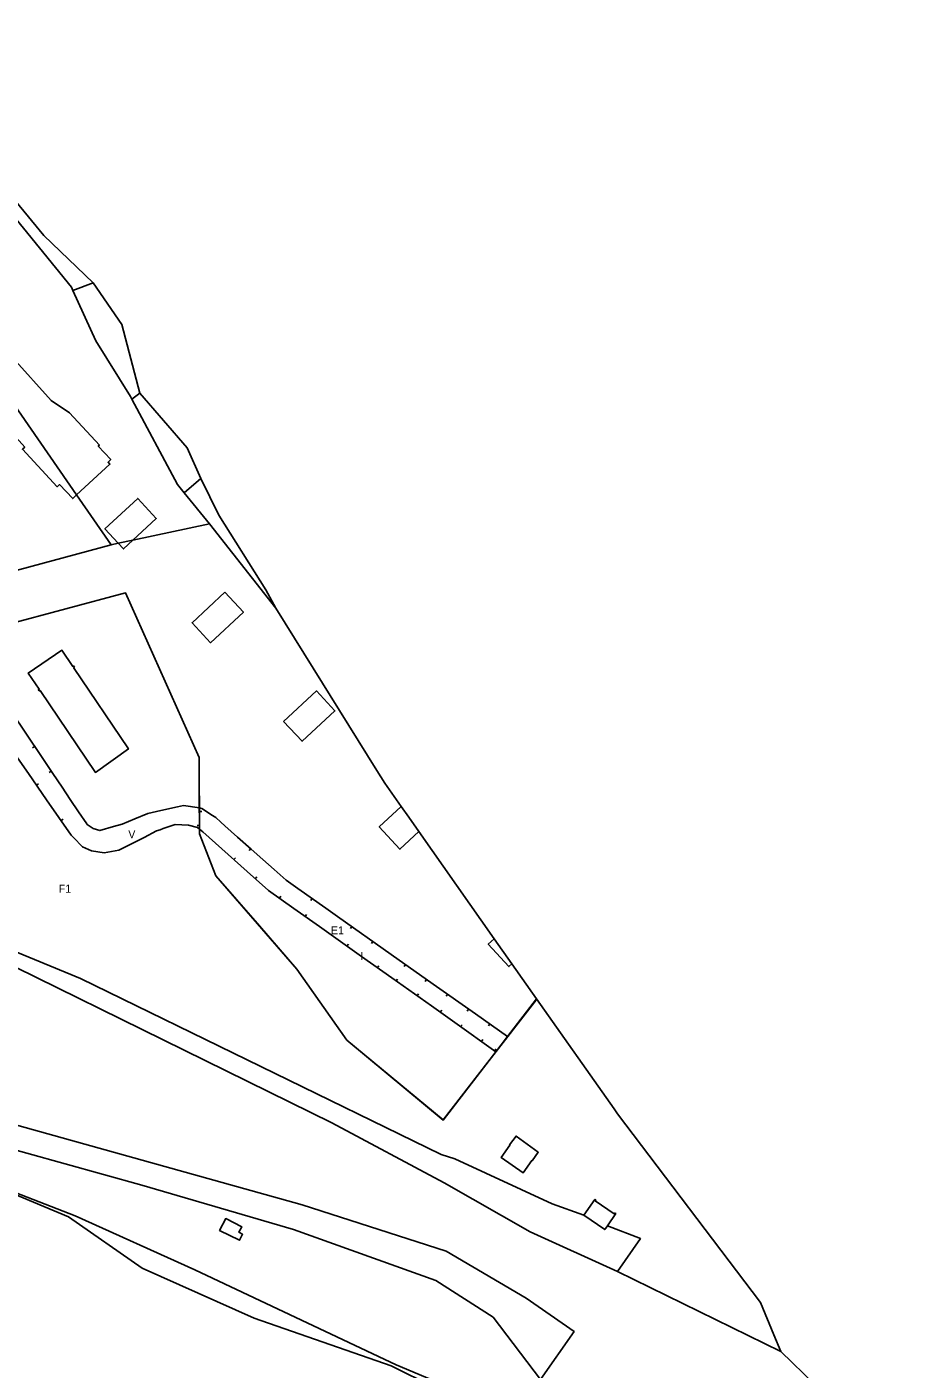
# Model space of a CAD drawing. Extents: x -749314 to -746497, y -1026537 to -1024935.
# Drawn here: x -747166.5 to -746888.2, y -1025946 to -1025526.8 of the extents above; entities that cross this region are included whole.
import ezdxf

# ---------------------------------------------------------------- set-up
doc = ezdxf.new("R2010")
doc.units = 0
for name, color, linetype in [('K_CD1', 7, 'Continuous'), ('K_DOSZDC1', 7, 'Continuous'), ('K_JVL', 7, 'Continuous'), ('K_NH_SZDC', 7, 'Continuous'), ('K_SZDC1', 7, 'Continuous'), ('K_VBP', 7, 'Continuous')]:
    doc.layers.add(name, color=color, linetype=linetype)

msp = doc.modelspace()

# ---------------------------------------------------------------- linework, layer by layer
for points in [[(-747164.06, -1025751.61), (-747164.69, -1025752.03)], [(-747158.89, -1025759.29), (-747159.51, -1025759.71)], [(-747163.47, -1025763.68), (-747162.85, -1025763.26)], [(-747112.61, -1025771.87), (-747111.86, -1025771.86)], [(-747155.8, -1025774.71), (-747155.18, -1025774.29)], [(-747112.58, -1025776.29), (-747113.33, -1025776.3)], [(-747101.81, -1025786.91), (-747101.31, -1025786.36)], [(-747096.56, -1025783.49), (-747097.06, -1025784.06)], [(-747095.15, -1025792.9), (-747094.65, -1025792.34)], [(-747087.65, -1025798.98), (-747087.22, -1025798.37)], [(-747077.37, -1025799.07), (-747077.81, -1025799.68)], [(-747079.64, -1025804.66), (-747079.2, -1025804.05)], [(-747064.99, -1025807.84), (-747065.43, -1025808.45)], [(-747066.53, -1025813.95), (-747066.09, -1025813.34)], [(-747058.46, -1025812.46), (-747058.9, -1025813.07)], [(-747057.06, -1025820.66), (-747056.62, -1025820.05)], [(-747048.23, -1025819.7), (-747048.66, -1025820.31)], [(-747051.2, -1025824.81), (-747050.77, -1025824.2)], [(-747041.69, -1025824.32), (-747042.12, -1025824.93)], [(-747044.67, -1025829.43), (-747044.24, -1025828.82)], [(-747035.09, -1025828.97), (-747035.53, -1025829.58)], [(-747037.39, -1025834.59), (-747036.95, -1025833.98)], [(-747028.55, -1025833.58), (-747028.99, -1025834.19)], [(-747031.04, -1025839.08), (-747030.61, -1025838.47)], [(-747021.96, -1025838.23), (-747022.39, -1025838.84)], [(-747024.52, -1025843.71), (-747024.08, -1025843.1)], [(-747019.74, -1025846.52), (-747020.34, -1025846.06)]]:
    msp.add_lwpolyline(points)
at = {"layer": 'K_CD1'}
for points in [[(-747145.79, -1025606.78), (-747161.2, -1025592.04), (-747186.31, -1025561.6), (-747208.9, -1025537.01), (-747217.97, -1025527.65), (-747211.2, -1025536.12), (-747152.53, -1025608.14), (-747152.08, -1025609.14)], [(-747200.27, -1025621.3), (-747167.16, -1025658.09), (-747167.86, -1025658.73), (-747156.98, -1025670.46), (-747156.24, -1025669.78), (-747152.14, -1025674.15), (-747150.94, -1025673.04), (-747185.44, -1025623.24), (-747188.83, -1025612.23), (-747194.35, -1025605.97), (-747201.01, -1025609.1), (-747196.13, -1025619.18)], [(-747131.2, -1025641.21), (-747136.83, -1025619.83), (-747145.79, -1025606.78), (-747152.08, -1025609.14), (-747144.94, -1025624.91), (-747134.13, -1025642.29), (-747133.71, -1025643.07)], [(-747180.93, -1025684.57), (-747178.68, -1025693.46), (-747204.73, -1025700.85), (-747205.8, -1025701.71), (-747198.39, -1025704.35), (-747140.17, -1025688.58), (-747150.94, -1025673.04), (-747152.14, -1025674.15), (-747156.24, -1025669.78), (-747156.98, -1025670.46), (-747167.86, -1025658.73), (-747167.16, -1025658.09), (-747200.27, -1025621.3), (-747211.67, -1025627.14), (-747214.25, -1025628.23), (-747203.49, -1025644.13), (-747199.44, -1025656.88), (-747194.73, -1025664.89), (-747194.07, -1025667.93), (-747191.35, -1025671.03), (-747185.48, -1025679.09)], [(-747116.4, -1025658.33), (-747131.2, -1025641.21), (-747133.71, -1025643.07), (-747119.48, -1025669.73), (-747117.33, -1025672.35), (-747112.18, -1025667.88)], [(-747112.18, -1025667.88), (-747117.33, -1025672.35), (-747109.43, -1025682), (-747088.77, -1025708.43), (-747091.9, -1025702.67), (-747106.55, -1025679.33)], [(-747137.97, -1025688.11), (-747133.41, -1025687.13), (-747126.09, -1025680.34), (-747131.87, -1025674.11), (-747142.13, -1025683.63)], [(-747137.97, -1025688.11), (-747136.35, -1025689.86), (-747133.41, -1025687.13)], [(-747104.66, -1025703.43), (-747114.92, -1025712.95), (-747109.14, -1025719.18), (-747098.88, -1025709.66)], [(-747104.66, -1025703.43), (-747114.92, -1025712.95), (-747109.14, -1025719.18), (-747098.88, -1025709.66)], [(-747086.35, -1025743.74), (-747080.57, -1025749.97), (-747070.31, -1025740.45), (-747076.09, -1025734.22)], [(-747086.35, -1025743.74), (-747080.57, -1025749.97), (-747070.31, -1025740.45), (-747076.09, -1025734.22)], [(-747049.6, -1025770.34), (-747056.45, -1025776.7), (-747049.99, -1025783.66), (-747044.08, -1025778.18), (-747047.27, -1025773.65)], [(-747015.98, -1025820.31), (-747015.04, -1025819.44), (-747020.55, -1025811.6), (-747022.44, -1025813.35)], [(-747023.69, -1025956.28), (-747051.16, -1025944.69), (-747114.03, -1025915.01), (-747151.35, -1025898.21), (-747190.83, -1025882.86), (-747153.53, -1025898.44), (-747130.44, -1025914.53), (-747095.48, -1025930.12), (-747052.77, -1025945.05), (-747025.84, -1025958.34)]]:
    msp.add_lwpolyline(points, close=True, dxfattribs=at)
for points in [[(-747185.44, -1025623.24), (-747150.94, -1025673.04), (-747140.57, -1025663.42), (-747141.14, -1025662.79), (-747140.27, -1025661.99), (-747144.18, -1025657.78), (-747143.85, -1025657.47), (-747153.18, -1025647.43), (-747158.88, -1025643.56), (-747194.93, -1025603.51)], [(-747198.39, -1025704.35), (-747140.17, -1025688.58), (-747137.97, -1025688.11), (-747136.35, -1025689.86), (-747133.41, -1025687.13), (-747109.43, -1025682), (-747088.77, -1025708.43), (-747057.23, -1025759.04), (-747054.75, -1025763.02), (-747049.6, -1025770.34), (-747056.45, -1025776.7), (-747049.99, -1025783.66), (-747044.08, -1025778.18), (-747020.55, -1025811.6), (-747022.44, -1025813.35), (-747015.98, -1025820.31), (-747015.04, -1025819.44), (-747007.32, -1025830.4), (-747016.39, -1025842.16), (-747020.03, -1025846.89), (-747036.47, -1025868.21), (-747066.55, -1025843.35), (-747082.15, -1025821.16), (-747107.45, -1025791.93), (-747112.56, -1025778.81), (-747112.73, -1025755.01), (-747135.65, -1025703.61), (-747172.98, -1025713.55)]]:
    msp.add_lwpolyline(points, dxfattribs=at)
at = {"layer": 'K_DOSZDC1'}
for points in [[(-747732.3, -1025526.84), (-747645.99, -1025568.28), (-747594.31, -1025595.17), (-747412.27, -1025689.89), (-747345.16, -1025724.81), (-747342.19, -1025721.29), (-747321.09, -1025732.24), (-747317.29, -1025742.74), (-747247.64, -1025780.1), (-747222.79, -1025794.6), (-747071.27, -1025869.13), (-747036.19, -1025887.86), (-747009.36, -1025903.18), (-746982.11, -1025915.51), (-746931.03, -1025940.57), (-746888.2, -1025982.16)], [(-747172.98, -1025713.55), (-747135.65, -1025703.61), (-747112.73, -1025755.01), (-747112.56, -1025778.81), (-747107.45, -1025791.93), (-747082.15, -1025821.16), (-747066.55, -1025843.35), (-747036.47, -1025868.21), (-747020.03, -1025846.89), (-747016.39, -1025842.16), (-747007.32, -1025830.4), (-746983.11, -1025864.79), (-746982.03, -1025866.32), (-746937.4, -1025925.27), (-746933.22, -1025935.31), (-746931.03, -1025940.57), (-746982.11, -1025915.51), (-746974.89, -1025905.27), (-746985.21, -1025901.23), (-746982.64, -1025897.47), (-746982.91, -1025897.28), (-746983.09, -1025897.54), (-746989.05, -1025893.47), (-746988.86, -1025893.19), (-746989.12, -1025893.01), (-746992.55, -1025898), (-747002.51, -1025894.46), (-747032.88, -1025880.32), (-747037.12, -1025878.96), (-747149.75, -1025824.07), (-747180.36, -1025811.49)], [(-747178.54, -1025875.29), (-747130.56, -1025888.54), (-747083.23, -1025902.44), (-747038.81, -1025918.38), (-747020.85, -1025929.84), (-747006.13, -1025949.27), (-746995.65, -1025934.33), (-747010.62, -1025923.86), (-747035.57, -1025909.17), (-747080.48, -1025894.72), (-747180.53, -1025866.82)], [(-747023.69, -1025956.28), (-747051.16, -1025944.69), (-747114.03, -1025915.01), (-747151.35, -1025898.21), (-747190.83, -1025882.86)]]:
    msp.add_lwpolyline(points, dxfattribs=at)
for points in [[(-747166.04, -1025728.64), (-747162.64, -1025733.67), (-747162.89, -1025733.84), (-747162.61, -1025734.23), (-747162.37, -1025734.07), (-747145.08, -1025759.67), (-747134.76, -1025752.36), (-747151.9, -1025726.96), (-747151.65, -1025726.79), (-747151.9, -1025726.42), (-747152.15, -1025726.59), (-747155.55, -1025721.55)], [(-747018.44, -1025879.9), (-747011.5, -1025884.7), (-747008.85, -1025880.92), (-747008.73, -1025881), (-747006.83, -1025878.28), (-747013.75, -1025873.26), (-747015.77, -1025876), (-747015.64, -1025876.09)], [(-747106.29, -1025902.73), (-747100.08, -1025905.79), (-747099.11, -1025903.89), (-747100.28, -1025903.3), (-747099.39, -1025901.56), (-747104.39, -1025899.01)]]:
    msp.add_lwpolyline(points, close=True, dxfattribs=at)
at = {"layer": 'K_JVL'}
for points in [[(-747071.27, -1025869.13), (-747036.19, -1025887.86), (-747009.36, -1025903.18), (-746982.11, -1025915.51), (-746974.89, -1025905.27), (-746985.21, -1025901.23), (-746986.05, -1025902.45), (-746992.55, -1025898), (-747002.51, -1025894.46), (-747032.88, -1025880.32), (-747037.12, -1025878.96), (-747149.75, -1025824.07), (-747180.36, -1025811.49), (-747220.97, -1025790.36), (-747222.79, -1025794.6)], [(-747099.11, -1025903.89), (-747100.28, -1025903.3), (-747099.39, -1025901.56), (-747104.39, -1025899.01), (-747106.29, -1025902.73), (-747100.08, -1025905.79)]]:
    msp.add_lwpolyline(points, close=True, dxfattribs=at)
at = {"layer": 'K_NH_SZDC'}
msp.add_lwpolyline([(-747195.11, -1025716.31), (-747178.16, -1025726.07), (-747172.98, -1025713.55), (-747135.65, -1025703.61), (-747112.73, -1025755.01), (-747112.65, -1025765.98), (-747112.56, -1025778.81), (-747107.45, -1025791.93), (-747093.88, -1025807.61), (-747082.15, -1025821.16), (-747066.55, -1025843.35), (-747060.4, -1025848.43), (-747036.46, -1025868.24), (-747022.18, -1025849.67), (-747007.3, -1025830.45)], dxfattribs=at)
at = {"layer": 'K_SZDC1'}
for points in [[(-747162.61, -1025734.23), (-747162.37, -1025734.07), (-747145.08, -1025759.67), (-747134.76, -1025752.36), (-747151.9, -1025726.96), (-747151.65, -1025726.79), (-747151.9, -1025726.42), (-747152.15, -1025726.59), (-747155.55, -1025721.55), (-747166.04, -1025728.64), (-747162.64, -1025733.67), (-747162.89, -1025733.84)], [(-747011.5, -1025884.7), (-747008.85, -1025880.92), (-747008.73, -1025881), (-747006.83, -1025878.28), (-747013.75, -1025873.26), (-747015.77, -1025876), (-747015.64, -1025876.09), (-747018.44, -1025879.9)], [(-746989.12, -1025893.01), (-746992.55, -1025898), (-746986.05, -1025902.45), (-746985.21, -1025901.23), (-746982.64, -1025897.47), (-746982.91, -1025897.28), (-746983.09, -1025897.54), (-746989.05, -1025893.47), (-746988.86, -1025893.19)]]:
    msp.add_lwpolyline(points, close=True, dxfattribs=at)
at = {"layer": 'K_VBP'}
msp.add_lwpolyline([(-747176.08, -1025733.78), (-747161.96, -1025754.73), (-747158.38, -1025760.04), (-747155.5, -1025764.31), (-747152.93, -1025768.13), (-747150.36, -1025771.95), (-747147.79, -1025775.76), (-747147.68, -1025775.99), (-747145.81, -1025777.23), (-747143.75, -1025777.83), (-747139.47, -1025776.62), (-747136.72, -1025775.84), (-747132.76, -1025774.16), (-747128.74, -1025772.46), (-747124.61, -1025771.56), (-747119.5, -1025770.45), (-747117.57, -1025770.03), (-747112.62, -1025770.79), (-747112.57, -1025777.37), (-747113.18, -1025776.86), (-747116.04, -1025776.17), (-747120.19, -1025775.95), (-747123.91, -1025777.24), (-747124.84, -1025777.56), (-747126, -1025777.96), (-747129.89, -1025779.97), (-747134, -1025782.09), (-747137.72, -1025784.01), (-747142.33, -1025784.78), (-747146.34, -1025784.16), (-747149.16, -1025782.96), (-747151.96, -1025779.98), (-747152.66, -1025779.23), (-747160.33, -1025768.2), (-747166.02, -1025760.02), (-747171.54, -1025752.01)], dxfattribs=at)
msp.add_lwpolyline([(-747112.62, -1025770.79), (-747111.81, -1025770.91), (-747108.51, -1025773.13), (-747107.51, -1025773.8), (-747105.96, -1025775.18), (-747104.64, -1025776.35), (-747100.68, -1025779.85), (-747096.43, -1025783.61), (-747092.76, -1025786.87), (-747089.25, -1025789.98), (-747085.5, -1025793.3), (-747081.86, -1025795.89), (-747073.12, -1025802.08), (-747069.48, -1025804.66), (-747052.72, -1025816.53), (-747039.59, -1025825.8), (-747026.45, -1025835.06), (-747016.39, -1025842.16), (-747020.03, -1025846.89), (-747032.9, -1025837.77), (-747040.18, -1025832.61), (-747052.57, -1025823.84), (-747062.04, -1025817.13), (-747070.78, -1025810.94), (-747075.15, -1025807.84), (-747083.16, -1025802.16), (-747091.06, -1025796.57), (-747097.72, -1025790.59), (-747105.59, -1025783.52), (-747109.52, -1025779.99), (-747111.51, -1025778.24), (-747112.57, -1025777.37)], close=True, dxfattribs=at)

# ---------------------------------------------------------------- texts
for s, p in [('V', (-747134.82, -1025780.25)), ('F1', (-747156.55, -1025797.25)), ('E1', (-747071.55, -1025810.25)), ('I', (-747062.41, -1025818.25))]:
    msp.add_text(s, height=2.5).set_placement(p)

doc.saveas('drawing.dxf')
